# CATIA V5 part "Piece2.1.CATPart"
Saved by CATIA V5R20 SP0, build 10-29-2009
Part number: Piece2.1
Bounding box of the stored display mesh (mm): x 0 to 100, y -50 to 228.37, z 86.603 to 298.759
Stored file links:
  C:\Users\Lambert\Desktop\IAO\Piece2.1.CATPart
  C:\Users\Lambert\Desktop\IAO\Produit1.CATProduct
  C:\Users\Lambert\Desktop\IAO\skl_general.CATPart
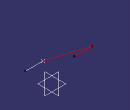
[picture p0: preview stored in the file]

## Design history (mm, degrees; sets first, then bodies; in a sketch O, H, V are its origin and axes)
Set1
  Line1 "Bielle 2.1": type PtPt, FirstPoint Point1, SecondPoint DatumPoint1, Support Plane1
  Line2 "Axe_pivot_12": type Normal, RefPoint Point1, RefSkin Plane1, Start 0, End 100
  Line3 "Axe_pivot_24": type Normal, RefPoint DatumPoint1, RefSkin Plane1, Start 0, End 100
Set2
  Point1 "B": linked copy from another document
  DatumPoint1 "E": linked copy from another document
  Plane1 "Plan_Ref": linked copy from another document
Body1 (main body)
